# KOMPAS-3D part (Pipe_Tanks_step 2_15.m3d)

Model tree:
1. X Axis
2. Y Axis
3. Z Axis  (labels: Pipe Dn 50)
     Òîëùèíà ñòåíêè 1 = 1

Referenced files in C:\Documents and Settings\kashirsky\Мои документы\Camtasia Studio\Pipelines3D\Tanks\: Tanks_step 2.a3d
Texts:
  Pipe Dn 50
  Steel ASTM A295
  Three Point Plane
  Plane at Angle
  Line and Point Plane
  Axis through Two Vertices
  Axis of Feature
  Axis of Conical Surface
  Axis through Edge
  Trim by Surface
  Trim by Sketch
  Feature with No History
  Intersection Axis of Two Planes
  Two Line Plane
  Line and Face Plane
  Bend by line
  Hole in sheet body
  Cut in sheet body
  Point in CM
  Linear Dimension from Line to Point
  Surface Finish Symbol
  Geometric Tolerance Symbol
  Leader #1
  Leader #2
  Leader #3
  Shape Deviations and Datum
  Node point number
  Mark of coordination axis
  Node point designation
  Mark/Reference designation with leader
  Mark/reference designation on line
  Mark/Reference designation without leader
  Plane of section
